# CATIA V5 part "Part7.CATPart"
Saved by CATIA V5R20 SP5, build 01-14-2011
Part number: 饮料瓶
Material "无"
Material "Black Leather": density 945 kg/m3
Material "DS Light Blue": density 7860 kg/m3, Young's modulus 2e+11 Pa, Poisson ratio 0.266
Bounding box of the stored display mesh (mm): x -25 to 26, y -25 to 25, z 0 to 110
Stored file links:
  E:\scc\Part7.CATPart
  C:\Program Files\Dassault Systemes\B20\intel_a\startup\materials\Catalog.CATMaterial
  C:\Program Files\Dassault Systemes\B20\intel_a\startup\materials\green_leather.jpg
  C:\Program Files\Dassault Systemes\B20\intel_a\startup\materials\black_leather.jpg
  C:\Program Files\Dassault Systemes\B20\intel_a\startup\materials\blue_env_512x512.jpg
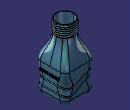
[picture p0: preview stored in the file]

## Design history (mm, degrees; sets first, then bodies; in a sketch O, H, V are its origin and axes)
Set1
  Sketch1 on xy-plane, origin (0, 0, 0), H (1, 0, 0), V (0, 1, 0)
    line L1 (25, 25) -> (25, -25)
    line L2 (25, -25) -> (-25, -25)
    line L3 (-25, -25) -> (-25, 25)
    line L4 (-25, 25) -> (25, 25)
    distance L2 L4 = 50
    distance L1 L3 = 50
    vertical: L1 V, L3 V
    horizontal: L2 H, L4 H
    equidistance: L1 L3 O, L2 L4 O
  Sketch2 on face of Pad1 from Sketch1.L2, origin (0, -25, 0), H (1, 0, 0), V (0, 0, 1)
    spline S1 through (-35.9543, 13.8001) (-9.9086, 25.806) (11.7961, 14.9169) (37.8418, 29.5753)
  Extrude1: Element1 Sketch2, Lim1 54, Lim2 54
  MultiSel1: CommonCtxFeats ({extract ExtractElem face of Pad1 from Sketch1.L1}; {extract ExtractElem face of Fillet1}; {extract ExtractElem face of Pad1 from Sketch1.L4}; {extract ExtractElem face of Fillet1}; {extract ExtractElem face of Pad1 from Sketch1.L3}; {extract ExtractElem face of Fillet1}; {extract ExtractElem face of Pad1 from Sketch1.L2}; {extract ExtractElem face of Fillet1})
  Sketch3 on face of Pad1 from Sketch1.L2, origin (0, -25, 0), H (1, 0, 0), V (0, 0, 1)
    spline S1 through (-34.9424, 28.6607) (-18.0311, 36.6468) (14.9014, 25.2887) (33.0588, 34.1623)
  Extrude2: Element1 Sketch3, Lim1 54, Lim2 54
  MultiSel2: CommonCtxFeats ({extract ExtractElem face of Pad1 from Sketch1.L2}; {extract ExtractElem face of Fillet1}; {extract ExtractElem face of Pad1 from Sketch1.L1}; {extract ExtractElem face of Fillet1}; {extract ExtractElem face of Pad1 from Sketch1.L4}; {extract ExtractElem face of Fillet1}; {extract ExtractElem face of Pad1 from Sketch1.L3}; {extract ExtractElem face of Fillet1})
  Join1: Elements ({intersect ToIntersect1 {extract ExtractElem face of Pad1 from Sketch1.L1}, ToIntersect2 Extrude1}; {intersect ToIntersect1 {extract ExtractElem face of Fillet1}, ToIntersect2 Extrude1}; {intersect ToIntersect1 {extract ExtractElem face of Pad1 from Sketch1.L4}, ToIntersect2 Extrude1}; {intersect ToIntersect1 {extract ExtractElem face of Fillet1}, ToIntersect2 Extrude1}; {intersect ToIntersect1 {extract ExtractElem face of Pad1 from Sketch1.L3}, ToIntersect2 Extrude1}; {intersect ToIntersect1 {extract ExtractElem face of Fillet1}, ToIntersect2 Extrude1}; {intersect ToIntersect1 {extract ExtractElem face of Pad1 from Sketch1.L2}, ToIntersect2 Extrude1}; {intersect ToIntersect1 {extract ExtractElem face of Fillet1}, ToIntersect2 Extrude1})
  Join2: Elements ({intersect ToIntersect1 {extract ExtractElem face of Pad1 from Sketch1.L4}, ToIntersect2 Extrude2}; {intersect ToIntersect1 {extract ExtractElem face of Fillet1}, ToIntersect2 Extrude2}; {intersect ToIntersect1 {extract ExtractElem face of Pad1 from Sketch1.L3}, ToIntersect2 Extrude2}; {intersect ToIntersect1 {extract ExtractElem face of Fillet1}, ToIntersect2 Extrude2}; {intersect ToIntersect1 {extract ExtractElem face of Pad1 from Sketch1.L2}, ToIntersect2 Extrude2}; {intersect ToIntersect1 {extract ExtractElem face of Fillet1}, ToIntersect2 Extrude2}; {intersect ToIntersect1 {extract ExtractElem face of Pad1 from Sketch1.L1}, ToIntersect2 Extrude2}; {intersect ToIntersect1 {extract ExtractElem face of Fillet1}, ToIntersect2 Extrude2})
  Plane1: type Normal, Curve Join2, RefPoint vertex [face of MultiSel2 | face of MultiSel2]
  Circle1: type CtrRad, Start 0, End 180, Center vertex [face of MultiSel2 | face of MultiSel2], FirstDirection (-1, 0, 0), Radius 1, Support Plane1
Body1 (main body), material "DS Light Blue"
  Pad1: profile Sketch1, direction (0, 0, 1), length 50
  Fillet1: on edge [face of Pad1 from Sketch1.L4 | face of Pad1 from Sketch1.L1]; edge [face of Pad1 from Sketch1.L1 | face of Pad1 from Sketch1.L2]; edge [face of Pad1 from Sketch1.L3 | face of Pad1 from Sketch1.L4]; edge [face of Pad1 from Sketch1.L2 | face of Pad1 from Sketch1.L3]
  Fillet2: on edge [start face of Pad1 | face of Pad1 from Sketch1.L3]
  Plane2: type Offset, RefPlane end face of Pad1, Offset 40, reversed
  Sketch4 on Plane2, origin (0, 0, 90), H (1, 0, 0), V (0, -1, 0)
    circle A1 centre (0, 0) radius 15
  Pad2: profile Sketch4, direction (0, 0, 1), length 20
  Sketch5 on end face of Pad1, origin (0, 0, 50), H (1, 0, 0), V (0, 1, 0)
    point P1 (25, 0)
    distance P1 O = 25
    coincidence: P1 H
  Sketch6 on start face of Pad2, origin (0, 0, 90), H (1, 0, 0), V (0, -1, 0)
    point P1 (15, 0)
    distance P1 V = 15
    coincidence: P1 H
  Loft1: solid, Sections ({boundary Boundary {extract ExtractElem start face of Pad2}}; {boundary Boundary {extract ExtractElem end face of Pad1}}), StartFace start face of Pad2, EndFace end face of Pad1
  Slot1: profile Circle1, centre curve Join2
  Plane3: type Normal, Curve Join1, RefPoint vertex [face of MultiSel1 | face of MultiSel1]
  Circle2: type CtrRad, Start 0, End 180, Center vertex [face of MultiSel1 | face of MultiSel1], Radius 1, FirstDirection (-1, 0, 0), Support Plane3
  Slot2: profile Circle2, centre curve Join1
  Shell1: ExtOffset 0, IntOffset 1, Face end face of Pad2
  Sketch7 on Plane2, origin (0, 0, 90), H (1, 0, 0), V (0, -1, 0)
    point P1 (15, 0)
    distance P1 O = 15
    coincidence: P1 H
  Plane4: type Offset, RefPlane Plane2, Offset 2, reversed
  Sketch8 on Plane4, origin (0, 0, 92), H (1, 0, 0), V (0, -1, 0)
    point P1 (15, 0)
    distance P1 O = 15
    coincidence: P1 H
  Helix1: Direction Z axis, RefPoint Sketch8, Pitch 3, Height 16, TaperAngle 0
  Point1: type OnCurve, Support Helix1, Length 5
  Line1: type PtDir, RefPoint Sketch8, Direction (1, 0, 0), Start 0, End 5
  Connect1: Curve1 Line1, Point1 vertex of Line1, Tension1 1, Curve2 Helix1, Point2 Point1, Tension2 1
  Point2: type OnCurve, Support Connect1, RefPoint vertex of Helix1, Length -5
  Line2: type PtDir, RefPoint vertex of Helix1, Direction (0, 1, 0), Start 0, End 5
  Connect2: Curve1 Line2, Point1 vertex of Line2, Tension1 1, Curve2 Connect1, Point2 Point2, Tension2 1
  Plane5: type Normal, Curve Connect2, RefPoint vertex of Connect2
  Circle3: type CtrRad, Start 0, End 180, Radius 1, Center vertex of Connect2, Support Plane5, FirstDirection (-1, 0, 0)
  Rib1: profile Circle3, centre curve Connect2
  Sketch9 on Plane2, origin (0, 0, 90), H (1, 0, 0), V (0, -1, 0)
    circle A1 centre (0, 0) radius 14
    radius A1 = 14
  Pocket1: profile Sketch9, direction (0, 0, 1), length 20
Body2, material "Black Leather"
  Sketch10 on face of Pad1 from Sketch1.L1, origin (25, 0, 0), H (0, 1, 0), V (0, 0, 1)
    polyline C1
    polyline C2
    polyline C3
    polyline C4
    polyline C5
    polyline C6
    polyline C7
    polyline C8
    polyline C9
    polyline C10
    polyline C11
    polyline C12
    polyline C13
  Pad3: profile Sketch10, direction (1, 0, 0), length 1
